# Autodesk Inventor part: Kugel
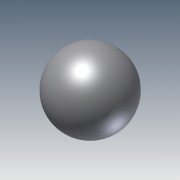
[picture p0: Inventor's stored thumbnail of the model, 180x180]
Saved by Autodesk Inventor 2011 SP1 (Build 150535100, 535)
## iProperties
Created: 2011-01
Part Number: Kugel
Document SubType Name: Modeling
Designer: Administrator
Density: 1 g/cm^3
Author: Administrator
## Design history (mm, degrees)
sketch "Skizze1"
  geometry: L1 (0, 3.5)-(0, -3.5); A1 r 3.5 centre (0, 0) between (0, -3.5) and (0, 3.5); 1 further point
  constraints: 2 end point, 2 point on circle, 1 centre point, 1 coincident, 1 vertical
  dimensions: "d0" = 90 deg dimension on point (0, 0) L1.end L1.start A1.centre A1 L1; "d1" = 3.5 radius of A1
revolve "Umdrehung1" sketch "Skizze1" stored, may be unused: angle "d0" = 90 deg
node "Volumenkörper1"
